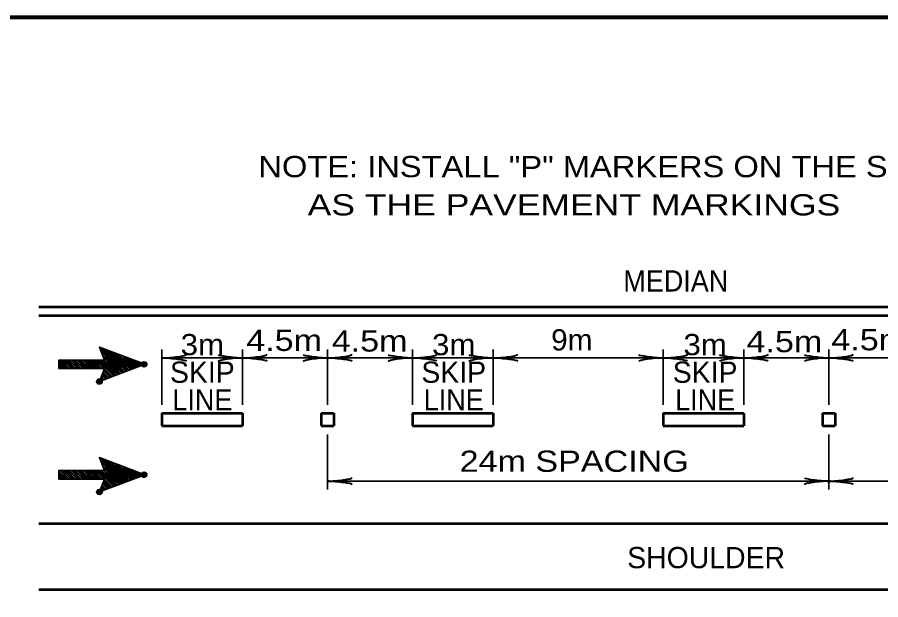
# Model space of a CAD drawing. Extents: x -96 to 617, y -65 to 388.
# Drawn here: x 320.7 to 422.4, y 314.5 to 383 of the extents above; entities that cross this region are included whole.
import ezdxf
from ezdxf.enums import TextEntityAlignment as Align

# ---------------------------------------------------------------- set-up
doc = ezdxf.new("R2010")
doc.units = 0
doc.header["$PDMODE"] = 32
doc.header["$PDSIZE"] = 0.5
doc.layers.add('1', color=7, linetype='Continuous', lineweight=53)

msp = doc.modelspace()

# ---------------------------------------------------------------- linework, layer by layer
at = {"layer": '1'}
for p, q in [((323.265, 348.913), (483.265, 348.913)), ((323.265, 347.913), (483.265, 347.913)), ((337.765, 336.413), (337.765, 334.913)), ((337.765, 336.413), (347.265, 336.413)), ((347.265, 336.413), (347.265, 334.913)), ((347.265, 336.413), (347.265, 334.913)), ((356.515, 336.413), (356.515, 334.913)), ((356.515, 336.413), (358.015, 336.413)), ((358.015, 336.413), (358.015, 334.913)), ((367.265, 336.413), (367.265, 334.913)), ((367.265, 336.413), (376.765, 336.413)), ((376.765, 336.413), (376.765, 334.913)), ((396.765, 336.413), (396.765, 334.913)), ((396.765, 336.413), (406.265, 336.413)), ((406.265, 336.413), (406.265, 334.913)), ((415.515, 336.413), (415.515, 334.913)), ((415.515, 336.413), (417.015, 336.413)), ((417.015, 336.413), (417.015, 334.913)), ((337.765, 334.913), (347.265, 334.913)), ((356.515, 334.913), (358.015, 334.913)), ((367.265, 334.913), (376.765, 334.913)), ((396.765, 334.913), (406.265, 334.913)), ((415.515, 334.913), (417.015, 334.913)), ((323.265, 323.413), (483.265, 323.413)), ((323.265, 315.663), (483.265, 315.663))]:
    msp.add_line(p, q, dxfattribs=at)
at = {"layer": '1', "lineweight": 35}
for p, q in [((330.399, 344.087), (333.335, 341.252)), ((330.5, 343.885), (333.234, 341.151)), ((330.602, 344.087), (333.437, 341.252)), ((330.602, 343.682), (333.133, 341.151)), ((330.804, 343.986), (333.538, 341.353)), ((331.007, 343.986), (333.639, 341.353)), ((331.31, 343.885), (333.74, 341.353)), ((331.513, 343.783), (333.842, 341.455)), ((331.715, 343.682), (333.943, 341.455)), ((331.918, 343.581), (334.044, 341.556)), ((337.765, 337.413), (337.765, 343.913)), ((347.265, 337.413), (347.265, 343.913)), ((357.265, 337.413), (357.265, 343.913)), ((367.265, 337.413), (367.265, 343.913)), ((376.765, 337.413), (376.765, 343.913)), ((396.765, 337.413), (396.765, 343.913)), ((406.265, 337.413), (406.265, 343.913)), ((416.265, 337.413), (416.265, 343.913)), ((325.64, 342.67), (331.007, 342.67)), ((325.64, 342.568), (326.552, 341.657)), ((325.742, 342.67), (326.754, 341.657)), ((325.843, 342.67), (326.855, 341.657)), ((326.045, 342.67), (327.058, 341.657)), ((326.147, 342.67), (327.159, 341.657)), ((326.349, 342.67), (327.362, 341.657)), ((326.45, 342.67), (327.463, 341.657)), ((326.552, 342.67), (327.564, 341.657)), ((326.754, 342.67), (327.767, 341.657)), ((326.855, 342.67), (327.868, 341.657)), ((327.058, 342.67), (328.07, 341.657)), ((327.159, 342.67), (328.172, 341.657)), ((327.26, 342.67), (328.273, 341.657)), ((327.463, 342.67), (328.475, 341.657)), ((327.564, 342.67), (328.577, 341.657)), ((327.767, 342.67), (328.779, 341.657)), ((327.868, 342.67), (328.88, 341.657)), ((328.07, 342.67), (329.083, 341.657)), ((328.172, 342.67), (329.184, 341.657)), ((328.273, 342.67), (329.285, 341.657)), ((328.475, 342.67), (329.488, 341.657)), ((328.577, 342.67), (329.589, 341.657)), ((328.779, 342.67), (329.792, 341.657)), ((328.88, 342.67), (329.893, 341.657)), ((328.982, 342.67), (329.994, 341.657)), ((329.184, 342.67), (330.197, 341.657)), ((329.285, 342.67), (330.298, 341.657)), ((329.488, 342.67), (330.5, 341.657)), ((329.589, 342.67), (330.602, 341.657)), ((329.69, 342.67), (330.703, 341.657)), ((329.893, 342.67), (330.905, 341.657)), ((329.994, 342.67), (331.918, 340.746)), ((330.197, 342.67), (332.12, 340.746)), ((330.298, 342.67), (332.222, 340.847)), ((330.5, 342.67), (332.323, 340.847)), ((330.602, 342.67), (332.424, 340.847)), ((330.703, 343.378), (333.032, 341.151)), ((330.703, 342.67), (332.525, 340.948)), ((330.804, 343.176), (332.93, 341.05)), ((330.905, 342.973), (332.829, 341.05)), ((330.905, 342.67), (332.627, 340.948)), ((331.007, 342.67), (332.728, 341.05)), ((332.222, 343.48), (334.145, 341.556)), ((332.424, 343.378), (334.247, 341.556)), ((332.627, 343.378), (334.348, 341.657)), ((332.93, 343.277), (334.449, 341.657)), ((333.133, 343.176), (334.55, 341.758)), ((333.335, 343.075), (334.652, 341.758)), ((333.538, 342.973), (334.753, 341.758)), ((333.842, 342.872), (334.854, 341.86)), ((334.044, 342.771), (334.955, 341.86)), ((334.247, 342.771), (335.057, 341.86)), ((334.449, 342.67), (335.158, 341.961)), ((334.753, 342.568), (335.259, 341.961)), ((325.64, 342.467), (326.45, 341.657)), ((325.64, 342.366), (326.349, 341.657)), ((325.64, 342.163), (326.147, 341.657)), ((325.64, 342.062), (326.045, 341.657)), ((325.64, 341.86), (325.843, 341.657)), ((325.64, 341.758), (325.742, 341.657)), ((331.007, 341.556), (331.817, 340.645)), ((334.955, 342.467), (335.36, 342.062)), ((335.158, 342.366), (335.462, 342.062)), ((335.36, 342.265), (335.563, 342.062)), ((330.602, 340.746), (331.007, 340.341)), ((330.602, 340.645), (330.905, 340.341)), ((330.602, 340.543), (330.804, 340.341)), ((330.703, 340.948), (331.209, 340.442)), ((330.703, 340.847), (331.108, 340.442)), ((330.804, 341.252), (331.513, 340.543)), ((330.804, 341.151), (331.412, 340.543)), ((330.804, 341.05), (331.31, 340.543)), ((330.905, 341.455), (331.715, 340.645)), ((330.905, 341.353), (331.614, 340.645)), ((330.399, 340.24), (330.5, 340.138)), ((330.5, 340.442), (330.703, 340.24)), ((330.5, 340.341), (330.602, 340.24)), ((357.265, 333.913), (357.265, 327.413)), ((416.265, 333.913), (416.265, 327.413)), ((330.399, 331.087), (333.335, 328.252)), ((330.5, 330.885), (333.234, 328.151)), ((330.602, 331.087), (333.437, 328.252)), ((330.602, 330.682), (333.133, 328.151)), ((330.703, 330.378), (333.032, 328.151)), ((330.804, 330.986), (333.538, 328.353)), ((331.007, 330.986), (333.639, 328.353)), ((331.31, 330.885), (333.74, 328.353)), ((331.513, 330.783), (333.842, 328.455)), ((331.715, 330.682), (333.943, 328.455)), ((331.918, 330.581), (334.044, 328.556)), ((332.222, 330.48), (334.145, 328.556)), ((332.424, 330.378), (334.247, 328.556)), ((332.627, 330.378), (334.348, 328.657)), ((325.64, 329.67), (331.007, 329.67)), ((325.64, 329.568), (326.552, 328.657)), ((325.64, 329.467), (326.45, 328.657)), ((325.64, 329.366), (326.349, 328.657)), ((325.742, 329.67), (326.754, 328.657)), ((325.843, 329.67), (326.855, 328.657)), ((326.045, 329.67), (327.058, 328.657)), ((326.147, 329.67), (327.159, 328.657)), ((326.349, 329.67), (327.362, 328.657)), ((326.45, 329.67), (327.463, 328.657)), ((326.552, 329.67), (327.564, 328.657)), ((326.754, 329.67), (327.767, 328.657)), ((326.855, 329.67), (327.868, 328.657)), ((327.058, 329.67), (328.07, 328.657)), ((327.159, 329.67), (328.172, 328.657)), ((327.26, 329.67), (328.273, 328.657)), ((327.463, 329.67), (328.475, 328.657)), ((327.564, 329.67), (328.577, 328.657)), ((327.767, 329.67), (328.779, 328.657)), ((327.868, 329.67), (328.88, 328.657)), ((328.07, 329.67), (329.083, 328.657)), ((328.172, 329.67), (329.184, 328.657)), ((328.273, 329.67), (329.285, 328.657)), ((328.475, 329.67), (329.488, 328.657)), ((328.577, 329.67), (329.589, 328.657)), ((328.779, 329.67), (329.792, 328.657)), ((328.88, 329.67), (329.893, 328.657)), ((328.982, 329.67), (329.994, 328.657)), ((329.184, 329.67), (330.197, 328.657)), ((329.285, 329.67), (330.298, 328.657)), ((329.488, 329.67), (330.5, 328.657)), ((329.589, 329.67), (330.602, 328.657)), ((329.69, 329.67), (330.703, 328.657)), ((329.893, 329.67), (330.905, 328.657)), ((329.994, 329.67), (331.918, 327.746)), ((330.197, 329.67), (332.12, 327.746)), ((330.298, 329.67), (332.222, 327.847)), ((330.5, 329.67), (332.323, 327.847)), ((330.602, 329.67), (332.424, 327.847)), ((330.703, 329.67), (332.525, 327.948)), ((330.804, 330.176), (332.93, 328.05)), ((330.905, 329.973), (332.829, 328.05)), ((330.905, 329.67), (332.627, 327.948)), ((331.007, 329.67), (332.728, 328.05)), ((332.93, 330.277), (334.449, 328.657)), ((333.133, 330.176), (334.55, 328.758)), ((333.335, 330.075), (334.652, 328.758)), ((333.538, 329.973), (334.753, 328.758)), ((333.842, 329.872), (334.854, 328.86)), ((334.044, 329.771), (334.955, 328.86)), ((334.247, 329.771), (335.057, 328.86)), ((334.449, 329.67), (335.158, 328.961)), ((334.753, 329.568), (335.259, 328.961)), ((334.955, 329.467), (335.36, 329.062)), ((335.158, 329.366), (335.462, 329.062)), ((325.64, 329.163), (326.147, 328.657)), ((325.64, 329.062), (326.045, 328.657)), ((325.64, 328.86), (325.843, 328.657)), ((325.64, 328.758), (325.742, 328.657)), ((330.905, 328.455), (331.715, 327.645)), ((330.905, 328.353), (331.614, 327.645)), ((331.007, 328.556), (331.817, 327.645)), ((335.36, 329.265), (335.563, 329.062)), ((330.5, 327.442), (330.703, 327.24)), ((330.5, 327.341), (330.602, 327.24)), ((330.602, 327.746), (331.007, 327.341)), ((330.602, 327.645), (330.905, 327.341)), ((330.602, 327.543), (330.804, 327.341)), ((330.703, 327.948), (331.209, 327.442)), ((330.703, 327.847), (331.108, 327.442)), ((330.804, 328.252), (331.513, 327.543)), ((330.804, 328.151), (331.412, 327.543)), ((330.804, 328.05), (331.31, 327.543)), ((330.399, 327.24), (330.5, 327.138))]:
    msp.add_line(p, q, dxfattribs=at)
at = {"layer": '1', "lineweight": 158}
msp.add_lwpolyline([(611.853, 383.009), (-47.897, 382.926), (-47.814, -55.407)], dxfattribs=at)
at = {"layer": '1', "lineweight": 35}
for points in [[(335.765, 342.163), (330.399, 340.138), (331.007, 341.657), (325.64, 341.657), (325.64, 342.67), (331.007, 342.67), (330.399, 344.188)], [(335.765, 329.163), (330.399, 327.138), (331.007, 328.657), (325.64, 328.657), (325.64, 329.67), (331.007, 329.67), (330.399, 331.188)]]:
    msp.add_lwpolyline(points, close=True, dxfattribs=at)
for points in [[(331.007, 341.657), (325.64, 341.657), (325.64, 342.67)], [(337.765, 342.913), (347.265, 342.913), (357.265, 342.913), (367.265, 342.913), (376.765, 342.913), (396.765, 342.913), (406.265, 342.913), (416.265, 342.913), (426.265, 342.913), (435.765, 342.913), (455.765, 342.913), (465.265, 342.913), (475.265, 342.913)], [(331.007, 328.657), (325.64, 328.657), (325.64, 329.67)], [(357.265, 328.413), (416.265, 328.413), (475.265, 328.413)]]:
    msp.add_lwpolyline(points, dxfattribs=at)
at = {"layer": '1', "lineweight": 40}
for centre, major_axis, ratio, start_param, end_param in [((338.886, 342.702), (-1.756, 0.176), 0.07063, 3.1407148, 5.41811), ((338.886, 342.702), (-1.756, 0.176), 0.07063, 3.1407148, 5.41811), ((338.857, 343.19), (-1.786, -0.156), 0.122415, 0.8963533, 3.1415927), ((338.857, 343.19), (-1.786, -0.156), 0.122415, 0.8963533, 3.1415927), ((346.174, 342.637), (1.786, 0.156), 0.122415, 0.8963533, 3.1415927), ((346.174, 342.637), (1.786, 0.156), 0.122415, 0.8963533, 3.1415927), ((346.145, 343.125), (1.756, -0.176), 0.07063, 3.1407148, 5.41811), ((346.145, 343.125), (1.756, -0.176), 0.07063, 3.1407148, 5.41811), ((348.386, 342.702), (-1.756, 0.176), 0.07063, 3.1407148, 5.41811), ((348.386, 342.702), (-1.756, 0.176), 0.07063, 3.1407148, 5.41811), ((348.357, 343.19), (-1.786, -0.156), 0.122415, 0.8963533, 3.1415927), ((348.357, 343.19), (-1.786, -0.156), 0.122415, 0.8963533, 3.1415927), ((356.174, 342.637), (1.786, 0.156), 0.122415, 0.8963533, 3.1415927), ((356.174, 342.637), (1.786, 0.156), 0.122415, 0.8963533, 3.1415927), ((356.145, 343.125), (1.756, -0.176), 0.07063, 3.1407148, 5.41811), ((356.145, 343.125), (1.756, -0.176), 0.07063, 3.1407148, 5.41811), ((358.386, 342.702), (-1.756, 0.176), 0.07063, 3.1407148, 5.41811), ((358.386, 342.702), (-1.756, 0.176), 0.07063, 3.1407148, 5.41811), ((358.357, 343.19), (-1.786, -0.156), 0.122415, 0.8963533, 3.1415927), ((358.357, 343.19), (-1.786, -0.156), 0.122415, 0.8963533, 3.1415927), ((366.174, 342.637), (1.786, 0.156), 0.122415, 0.8963533, 3.1415927), ((366.174, 342.637), (1.786, 0.156), 0.122415, 0.8963533, 3.1415927), ((366.145, 343.125), (1.756, -0.176), 0.07063, 3.1407148, 5.41811), ((366.145, 343.125), (1.756, -0.176), 0.07063, 3.1407148, 5.41811), ((368.386, 342.702), (-1.756, 0.176), 0.07063, 3.1407148, 5.41811), ((368.386, 342.702), (-1.756, 0.176), 0.07063, 3.1407148, 5.41811), ((368.357, 343.19), (-1.786, -0.156), 0.122415, 0.8963533, 3.1415927), ((368.357, 343.19), (-1.786, -0.156), 0.122415, 0.8963533, 3.1415927), ((375.674, 342.637), (1.786, 0.156), 0.122415, 0.8963533, 3.1415927), ((375.674, 342.637), (1.786, 0.156), 0.122415, 0.8963533, 3.1415927), ((375.645, 343.125), (1.756, -0.176), 0.07063, 3.1407148, 5.41811), ((375.645, 343.125), (1.756, -0.176), 0.07063, 3.1407148, 5.41811), ((377.886, 342.702), (-1.756, 0.176), 0.07063, 3.1407148, 5.41811), ((377.886, 342.702), (-1.756, 0.176), 0.07063, 3.1407148, 5.41811), ((377.857, 343.19), (-1.786, -0.156), 0.122415, 0.8963533, 3.1415927), ((377.857, 343.19), (-1.786, -0.156), 0.122415, 0.8963533, 3.1415927), ((395.674, 342.637), (1.786, 0.156), 0.122415, 0.8963533, 3.1415927), ((395.674, 342.637), (1.786, 0.156), 0.122415, 0.8963533, 3.1415927), ((395.645, 343.125), (1.756, -0.176), 0.07063, 3.1407148, 5.41811), ((395.645, 343.125), (1.756, -0.176), 0.07063, 3.1407148, 5.41811), ((397.886, 342.702), (-1.756, 0.176), 0.07063, 3.1407148, 5.41811), ((397.886, 342.702), (-1.756, 0.176), 0.07063, 3.1407148, 5.41811), ((397.857, 343.19), (-1.786, -0.156), 0.122415, 0.8963533, 3.1415927), ((397.857, 343.19), (-1.786, -0.156), 0.122415, 0.8963533, 3.1415927), ((405.174, 342.637), (1.786, 0.156), 0.122415, 0.8963533, 3.1415927), ((405.174, 342.637), (1.786, 0.156), 0.122415, 0.8963533, 3.1415927), ((405.145, 343.125), (1.756, -0.176), 0.07063, 3.1407148, 5.41811), ((405.145, 343.125), (1.756, -0.176), 0.07063, 3.1407148, 5.41811), ((407.386, 342.702), (-1.756, 0.176), 0.07063, 3.1407148, 5.41811), ((407.386, 342.702), (-1.756, 0.176), 0.07063, 3.1407148, 5.41811), ((407.357, 343.19), (-1.786, -0.156), 0.122415, 0.8963533, 3.1415927), ((407.357, 343.19), (-1.786, -0.156), 0.122415, 0.8963533, 3.1415927), ((415.174, 342.637), (1.786, 0.156), 0.122415, 0.8963533, 3.1415927), ((415.174, 342.637), (1.786, 0.156), 0.122415, 0.8963533, 3.1415927), ((415.145, 343.125), (1.756, -0.176), 0.07063, 3.1407148, 5.41811), ((415.145, 343.125), (1.756, -0.176), 0.07063, 3.1407148, 5.41811), ((417.386, 342.702), (-1.756, 0.176), 0.07063, 3.1407148, 5.41811), ((417.386, 342.702), (-1.756, 0.176), 0.07063, 3.1407148, 5.41811), ((417.357, 343.19), (-1.786, -0.156), 0.122415, 0.8963533, 3.1415927), ((417.357, 343.19), (-1.786, -0.156), 0.122415, 0.8963533, 3.1415927), ((358.386, 328.202), (-1.756, 0.176), 0.07063, 3.1407148, 5.41811), ((358.386, 328.202), (-1.756, 0.176), 0.07063, 3.1407148, 5.41811), ((358.357, 328.69), (-1.786, -0.156), 0.122415, 0.8963533, 3.1415927), ((358.357, 328.69), (-1.786, -0.156), 0.122415, 0.8963533, 3.1415927), ((415.174, 328.137), (1.786, 0.156), 0.122415, 0.8963533, 3.1415927), ((415.174, 328.137), (1.786, 0.156), 0.122415, 0.8963533, 3.1415927), ((415.145, 328.625), (1.756, -0.176), 0.07063, 3.1407148, 5.41811), ((415.145, 328.625), (1.756, -0.176), 0.07063, 3.1407148, 5.41811), ((417.386, 328.202), (-1.756, 0.176), 0.07063, 3.1407148, 5.41811), ((417.386, 328.202), (-1.756, 0.176), 0.07063, 3.1407148, 5.41811), ((417.357, 328.69), (-1.786, -0.156), 0.122415, 0.8963533, 3.1415927), ((417.357, 328.69), (-1.786, -0.156), 0.122415, 0.8963533, 3.1415927)]:
    msp.add_ellipse(centre, major_axis=major_axis, ratio=ratio, start_param=start_param, end_param=end_param, dxfattribs=at)
at = {"layer": '1'}
for p in [(335.664, 342.163), (330.399, 340.138), (335.664, 329.163), (330.399, 327.138)]:
    msp.add_point(p, dxfattribs=at)

# ---------------------------------------------------------------- texts
for s, width, p in [('NOTE: INSTALL "P" MARKERS ON THE SAME ALIGNMENT', 1.15, (349.111, 364.186)), ('     AS THE PAVEMENT MARKINGS', 1.25, (349.111, 359.686))]:
    msp.add_text(s, height=2.5, dxfattribs=dict(at, width=width)).set_placement(p)
for s, width, p in [('MEDIAN', 0.95, (398.254, 350.731)), ('3m', 1.1, (342.522, 343.238)), ('4.5m', 1.2, (352.148, 343.739)), ('4.5m', 1.2, (362.21, 343.665)), ('3m', 1.1, (372.115, 343.238)), ('9m', 1.05, (386.012, 343.794)), ('3m', 1.1, (401.707, 343.238)), ('4.5m', 1.2, (411.038, 343.591)), ('4.5m', 1.2, (421.026, 343.813)), ('LINE', 0.95, (342.522, 336.738)), ('LINE', 0.95, (372.115, 336.738)), ('LINE', 0.95, (401.707, 336.738)), ('24m SPACING', 1.2, (386.293, 329.513))]:
    msp.add_text(s, height=2.5, dxfattribs=dict(at, width=width)).set_placement(p, align=Align.CENTER)
for s, p in [('SKIP', (342.522, 339.988)), ('SKIP', (372.115, 339.988)), ('SKIP', (401.707, 339.988)), ('SHOULDER', (401.824, 318.169))]:
    msp.add_text(s, height=2.5, dxfattribs=at).set_placement(p, align=Align.CENTER)

doc.saveas('drawing.dxf')
